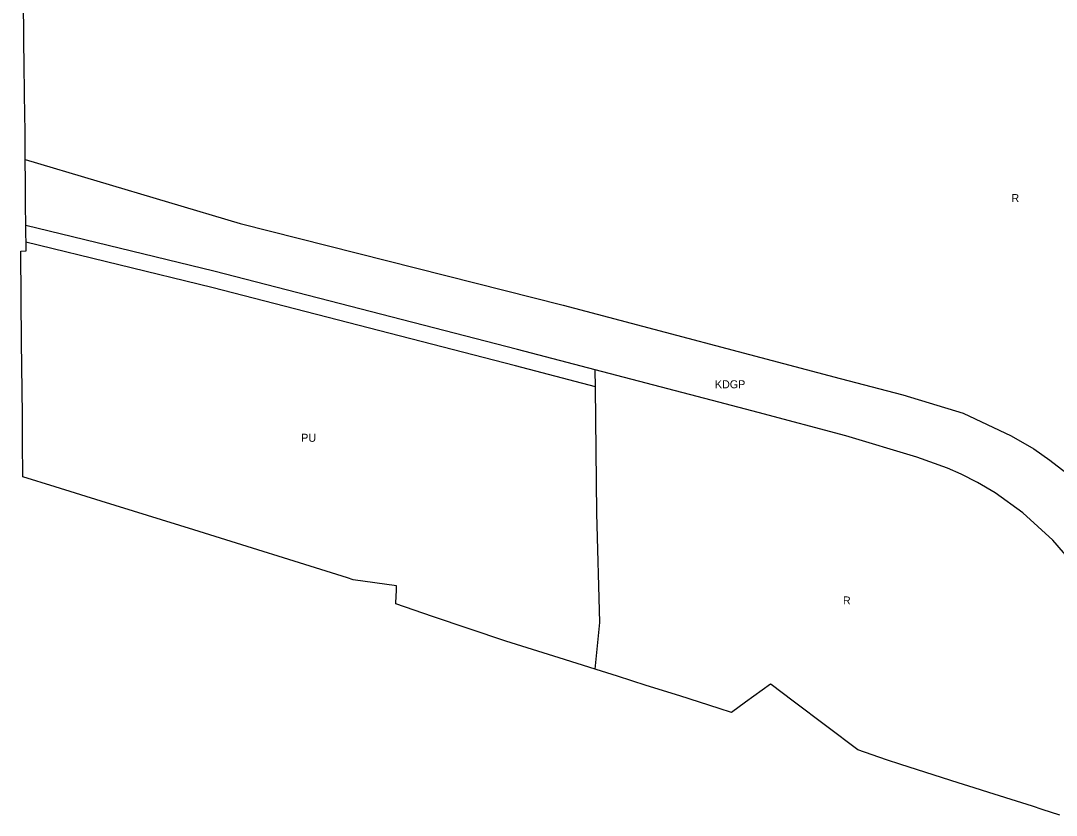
# Model space of a CAD drawing. Extents: x 7435758 to 7439981, y 5550649 to 5554049.
# Drawn here: x 7435762 to 7436435, y 5550705 to 5551221 of the extents above; entities that cross this region are included whole.
import ezdxf

# ---------------------------------------------------------------- set-up
doc = ezdxf.new("R2010")
doc.units = 0
for name, color, linetype in [('linie_rozgraniczające', 7, 'Continuous'), ('linie_zabudowy_nieprzekraczalne', 7, 'Continuous'), ('oznaczenia_przeznaczen', 7, 'Continuous')]:
    doc.layers.add(name, color=color, linetype=linetype)

msp = doc.modelspace()

# ---------------------------------------------------------------- linework, layer by layer
at = {"layer": 'linie_rozgraniczające'}
for p, q in [((7435764.25, 5551208.63), (7435763.61, 5551283.25)), ((7435764.51, 5551191.99), (7435764.25, 5551208.63)), ((7435764.91, 5551158.91), (7435764.51, 5551191.99)), ((7435764.98, 5551151.26), (7435764.91, 5551158.91)), ((7435765.15, 5551131.22), (7435764.98, 5551151.26)), ((7435765.29, 5551116.27), (7435765.15, 5551131.22)), ((7435765.15, 5551131.22), (7435904.79, 5551089.77)), ((7435765.4, 5551101.83), (7435765.29, 5551116.27)), ((7435765.51, 5551088.35), (7435765.4, 5551101.83)), ((7435765.64, 5551071.82), (7435765.51, 5551088.35)), ((7435765.58, 5551088.33), (7435765.51, 5551088.35)), ((7435887.7, 5551058.7), (7435765.58, 5551088.33)), ((7435904.79, 5551089.77), (7436114.66, 5551036.51)), ((7435762.19, 5551071.7), (7435765.64, 5551071.82)), ((7435762.39, 5551040.78), (7435762.19, 5551071.7)), ((7436085.1, 5551007.68), (7435887.7, 5551058.7)), ((7435762.64, 5551012.85), (7435762.39, 5551040.78)), ((7436114.66, 5551036.51), (7436294.74, 5550989.01)), ((7435763.34, 5550965.24), (7435762.64, 5551012.85)), ((7436135.49, 5550994.57), (7436085.1, 5551007.68)), ((7436135.62, 5550983.1), (7436135.49, 5550994.57)), ((7436215.91, 5550973.64), (7436135.49, 5550994.57)), ((7436294.74, 5550989.01), (7436335.4, 5550978.35)), ((7436136.52, 5550901.45), (7436135.62, 5550983.1)), ((7436335.4, 5550978.35), (7436374.57, 5550966.32)), ((7436241.45, 5550966.83), (7436215.91, 5550973.64)), ((7435763.42, 5550948.08), (7435763.34, 5550965.24)), ((7436298.41, 5550951.66), (7436241.45, 5550966.83)), ((7436374.57, 5550966.32), (7436405.88, 5550951.72)), ((7435763.51, 5550925.12), (7435763.42, 5550948.08)), ((7436344.55, 5550937.88), (7436298.41, 5550951.66)), ((7436405.88, 5550951.72), (7436420.6, 5550943.16)), ((7436420.6, 5550943.16), (7436431, 5550935.96)), ((7436364.57, 5550930.77), (7436344.55, 5550937.88)), ((7436431, 5550935.96), (7436441.38, 5550927.82)), ((7436373.43, 5550926.75), (7436364.57, 5550930.77)), ((7436383.92, 5550921.41), (7436373.43, 5550926.75)), ((7435784.64, 5550918.55), (7435763.51, 5550925.12)), ((7436395.5, 5550914.63), (7436383.92, 5550921.41)), ((7435814.4, 5550909.29), (7435784.64, 5550918.55)), ((7436413.46, 5550901.74), (7436395.5, 5550914.63)), ((7435874.67, 5550890.52), (7435814.4, 5550909.29)), ((7436138.61, 5550830.48), (7436136.52, 5550901.45)), ((7436432.85, 5550883.86), (7436413.46, 5550901.74)), ((7435974.65, 5550859.35), (7435874.67, 5550890.52)), ((7436443.93, 5550871.08), (7436432.85, 5550883.86)), ((7435978.32, 5550858.2), (7435974.65, 5550859.35)), ((7436006.48, 5550854.12), (7435978.32, 5550858.2)), ((7436006.36, 5550850.64), (7436006.48, 5550854.12)), ((7436005.91, 5550842.53), (7436006.2, 5550847.84)), ((7436006.2, 5550847.84), (7436006.36, 5550850.64)), ((7436029.8, 5550834.35), (7436005.91, 5550842.53)), ((7436077.4, 5550818.3), (7436029.8, 5550834.35)), ((7436135.59, 5550800.02), (7436138.61, 5550830.48)), ((7436112.15, 5550807.35), (7436077.4, 5550818.3)), ((7436135.59, 5550800.02), (7436112.15, 5550807.35)), ((7436136.22, 5550799.82), (7436135.59, 5550800.02)), ((7436149.93, 5550795.5), (7436136.22, 5550799.82)), ((7436168.72, 5550789.5), (7436149.93, 5550795.5)), ((7436190.45, 5550782.64), (7436168.72, 5550789.5)), ((7436249.41, 5550790.39), (7436233.28, 5550778.56)), ((7436249.96, 5550790.09), (7436249.41, 5550790.39)), ((7436264.2, 5550779.34), (7436249.96, 5550790.09)), ((7436216.07, 5550774.54), (7436190.45, 5550782.64)), ((7436233.28, 5550778.56), (7436224.18, 5550771.87)), ((7436286.05, 5550762.79), (7436264.2, 5550779.34)), ((7436224.18, 5550771.87), (7436216.07, 5550774.54)), ((7436306.16, 5550747.55), (7436286.05, 5550762.79)), ((7436324.74, 5550741.04), (7436306.16, 5550747.55)), ((7436334.23, 5550738.08), (7436324.74, 5550741.04)), ((7436371.49, 5550726.27), (7436334.23, 5550738.08)), ((7436381.87, 5550722.98), (7436371.49, 5550726.27)), ((7436391.36, 5550719.99), (7436381.87, 5550722.98)), ((7436412.77, 5550713.23), (7436391.36, 5550719.99)), ((7436419.75, 5550710.93), (7436412.77, 5550713.23)), ((7436426.03, 5550708.86), (7436419.75, 5550710.93)), ((7436437.48, 5550705.09), (7436426.03, 5550708.86))]:
    msp.add_line(p, q, dxfattribs=at)
at = {"layer": 'linie_zabudowy_nieprzekraczalne'}
msp.add_lwpolyline([(7436135.75, 5550983.61), (7436083.83, 5550997.16), (7435886.49, 5551048.17), (7435765.61, 5551077.5)], dxfattribs=at)

# ---------------------------------------------------------------- texts
at = {"layer": 'oznaczenia_przeznaczen'}
for s, p in [('R', (7436406.06, 5551103.58)), ('KDGP', (7436213.34, 5550982.58)), ('PU', (7435944.48, 5550947.81)), ('R', (7436296.53, 5550842.08))]:
    msp.add_text(s, height=5.2, dxfattribs=at).set_placement(p)

doc.saveas('drawing.dxf')
